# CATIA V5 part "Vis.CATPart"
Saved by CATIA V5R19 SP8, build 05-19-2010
Part number: Vis
Nomenclature: 70_k
Bounding box of the stored display mesh (mm): x -9.5 to 9.5, y -9.499 to 9.5, z 0 to 141
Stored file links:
  C:\Users\rphgr\Desktop\0_Tapis_TC520B_vitesse\Vis.CATPart
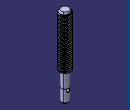
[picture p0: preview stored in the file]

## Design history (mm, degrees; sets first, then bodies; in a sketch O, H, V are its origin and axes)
Body1 (main body)
  AxisSystem1: origin (0, 0, 0), X (1, 0, 0), Y (0, 1, 0), Z (0, 0, 1)
  Sketch1 on ZX plane of AxisSystem1, origin (0, 0, 0), H (0, 0, 1), V (1, 0, 0)
    axis line L1 (-8.4468, 0) -> (91.9456, 0)
    point P1 (-8.4468, 0)
    line L2 (0, 0) -> (0, 6)
    line L3 (0, 6) -> (22.1235, 6)
    line L4 (22.1235, 6) -> (47, 6)
    line L5 (47, 6) -> (47, 6.65)
    line L6 (47, 6.65) -> (49, 6.65)
    line L7 (49, 6.65) -> (49, 9.5)
    line L8 (49, 9.5) -> (141, 9.5)
    line L9 (141, 9.5) -> (141, 0)
    point P10 (141, 0)
    distance L3 L1 = 6
    distance L6 L1 = 6.65
    distance L8 L1 = 9.5
    distance L2 L5 = 47
    distance L5 L7 = 2
    distance L2 L9 = 141
    coincidence: P1 H, P10 L1
    horizontal: L1 H, L3 H, L4 H, L6 H, L8 H
    vertical: L2 V, L5 V, L7 V, L9 V
  Shaft1: profile Sketch1, axis Sketch1.L1, angle 360
  Chamfer1: length 1, angle 45, on face of Shaft1 from Sketch1.L2
  Fillet1: radius 2, on edge [face of Shaft1 from Sketch1.L6 | face of Shaft1 from Sketch1.L7]
  Chamfer2: length 5, angle 30, on face of Shaft1 from Sketch1.L9
  Sketch2 on ZX plane of AxisSystem1, origin (0, 0, 0), H (0, 0, 1), V (1, 0, 0)
    line L1 (45, 0) -> (45, 9.5)
    point P1 (45, 0)
    point P2 (45, 9.5)
    reference intersected line E1 through (49, 0) direction (0, 1) from face of Shaft1 from Sketch1.L7
    length L1 = 9.5
    distance L1 E1 = 4
    coincidence: P1 H
    vertical: L1 V
  Helix1: Direction Z axis, RefPoint Sketch2.P2, Pitch 3, Height 100, TaperAngle 0
  Sketch3 on ZX plane of AxisSystem1, origin (0, 0, 0), H (0, 0, 1), V (1, 0, 0)
    point P1 (49, 9.5)
    line L1 (49, 9.5) -> (50.9019, 9.5)
    line L2 (50.9019, 9.5) -> (50.5, 8)
    line L3 (50.5, 8) -> (49.4019, 8)
    line L4 (49.4019, 8) -> (49, 9.5)
    axis line L5 (49.201, 8.75) -> (50.701, 8.75)
    point P5 (49.201, 8.75)
    point P6 (50.701, 8.75)
    reference projected line E1 through (0, 0) direction (1, 0) from axis of face of Shaft1 from Sketch1.L8
    reference intersected line E2 through (49, 0) direction (0, 1) from face of Shaft1 from Sketch1.L7
    reference projected line E3 through (0, 0) direction (1, 0) from axis of face of Shaft1 from Sketch1.L8
    angle L4 L2 = 30
    angle L1 L2 = 75
    distance L5 L1 = 0.75
    distance L1 E1 = 9.5
    distance L3 E3 = 8
    length L5 = 1.5
    horizontal: L1 H, L3 H, L5 H
    coincidence: P5 L4, P6 L2, P1 E2
  Slot1: profile Sketch3, centre curve Helix1
  Sketch4 on ZX plane of AxisSystem1, origin (0, 0, 0), H (0, 0, 1), V (1, 0, 0)
    circle A1 centre (19, 0) radius 2.5
    point P1 (19, 0)
    reference intersected line E1 (0, -6) -> (0, 6) from face of Shaft1 from Sketch1.L2
    radius A1 = 2.5
    distance E1 P1 = 19
    coincidence: P1 H
  Pocket1: profile Sketch4, direction (0, -1, 0), length 20, mirrored extent
  Chamfer3: length 1, angle 30, on face of Pocket1 from Sketch4.A1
